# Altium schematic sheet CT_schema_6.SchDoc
size 577 x 363 mm
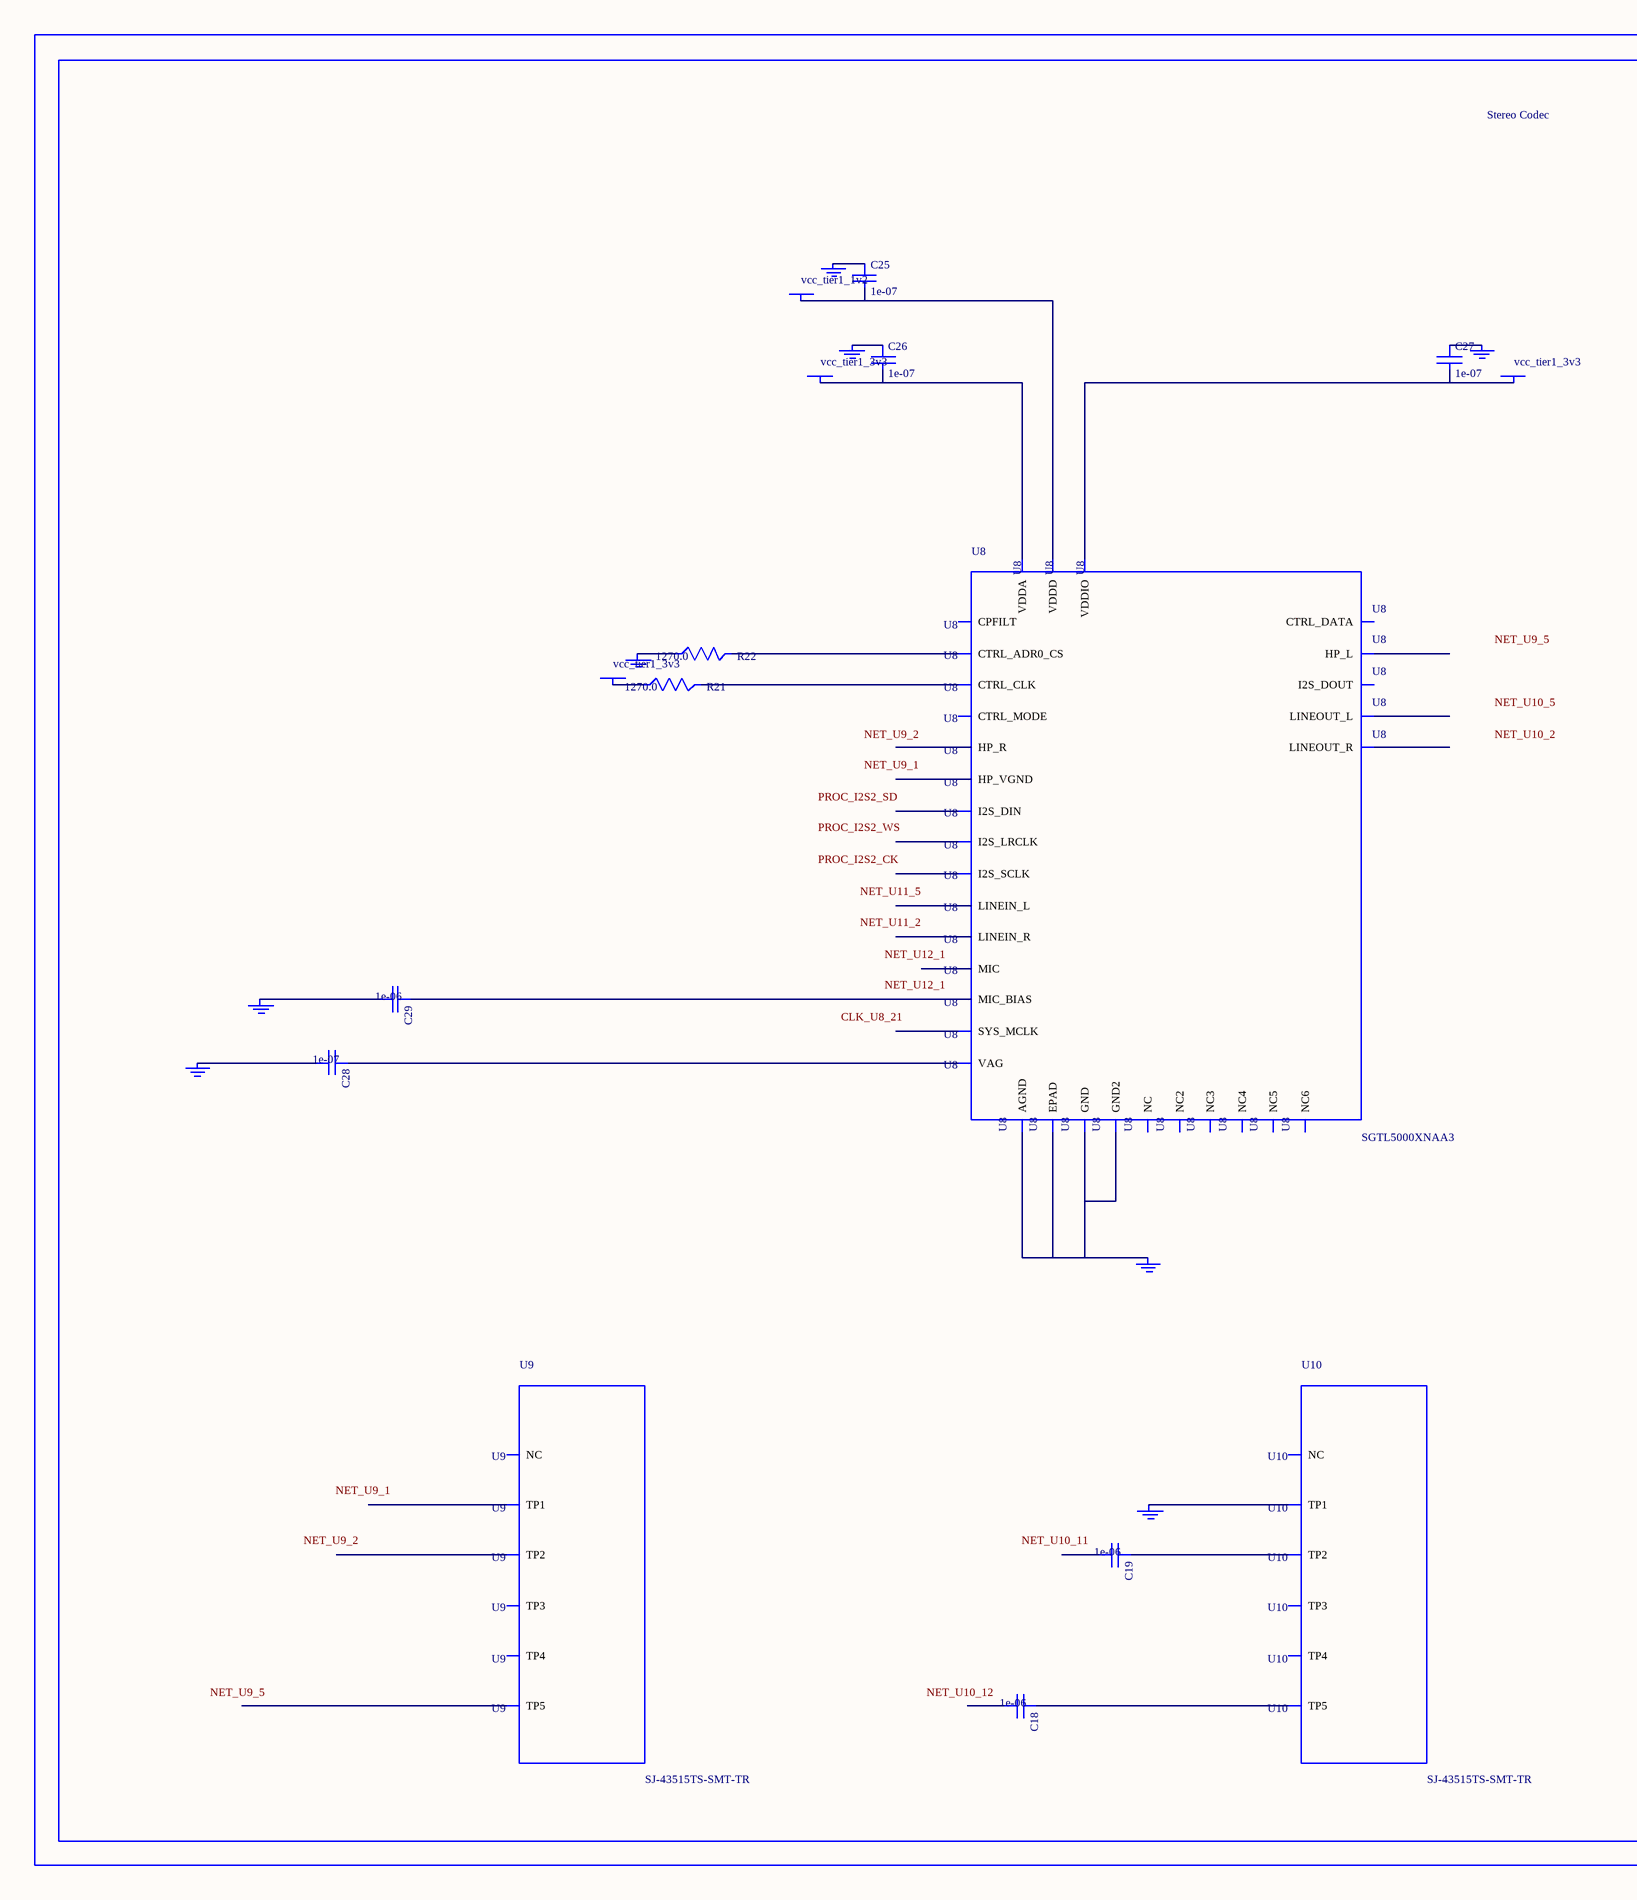
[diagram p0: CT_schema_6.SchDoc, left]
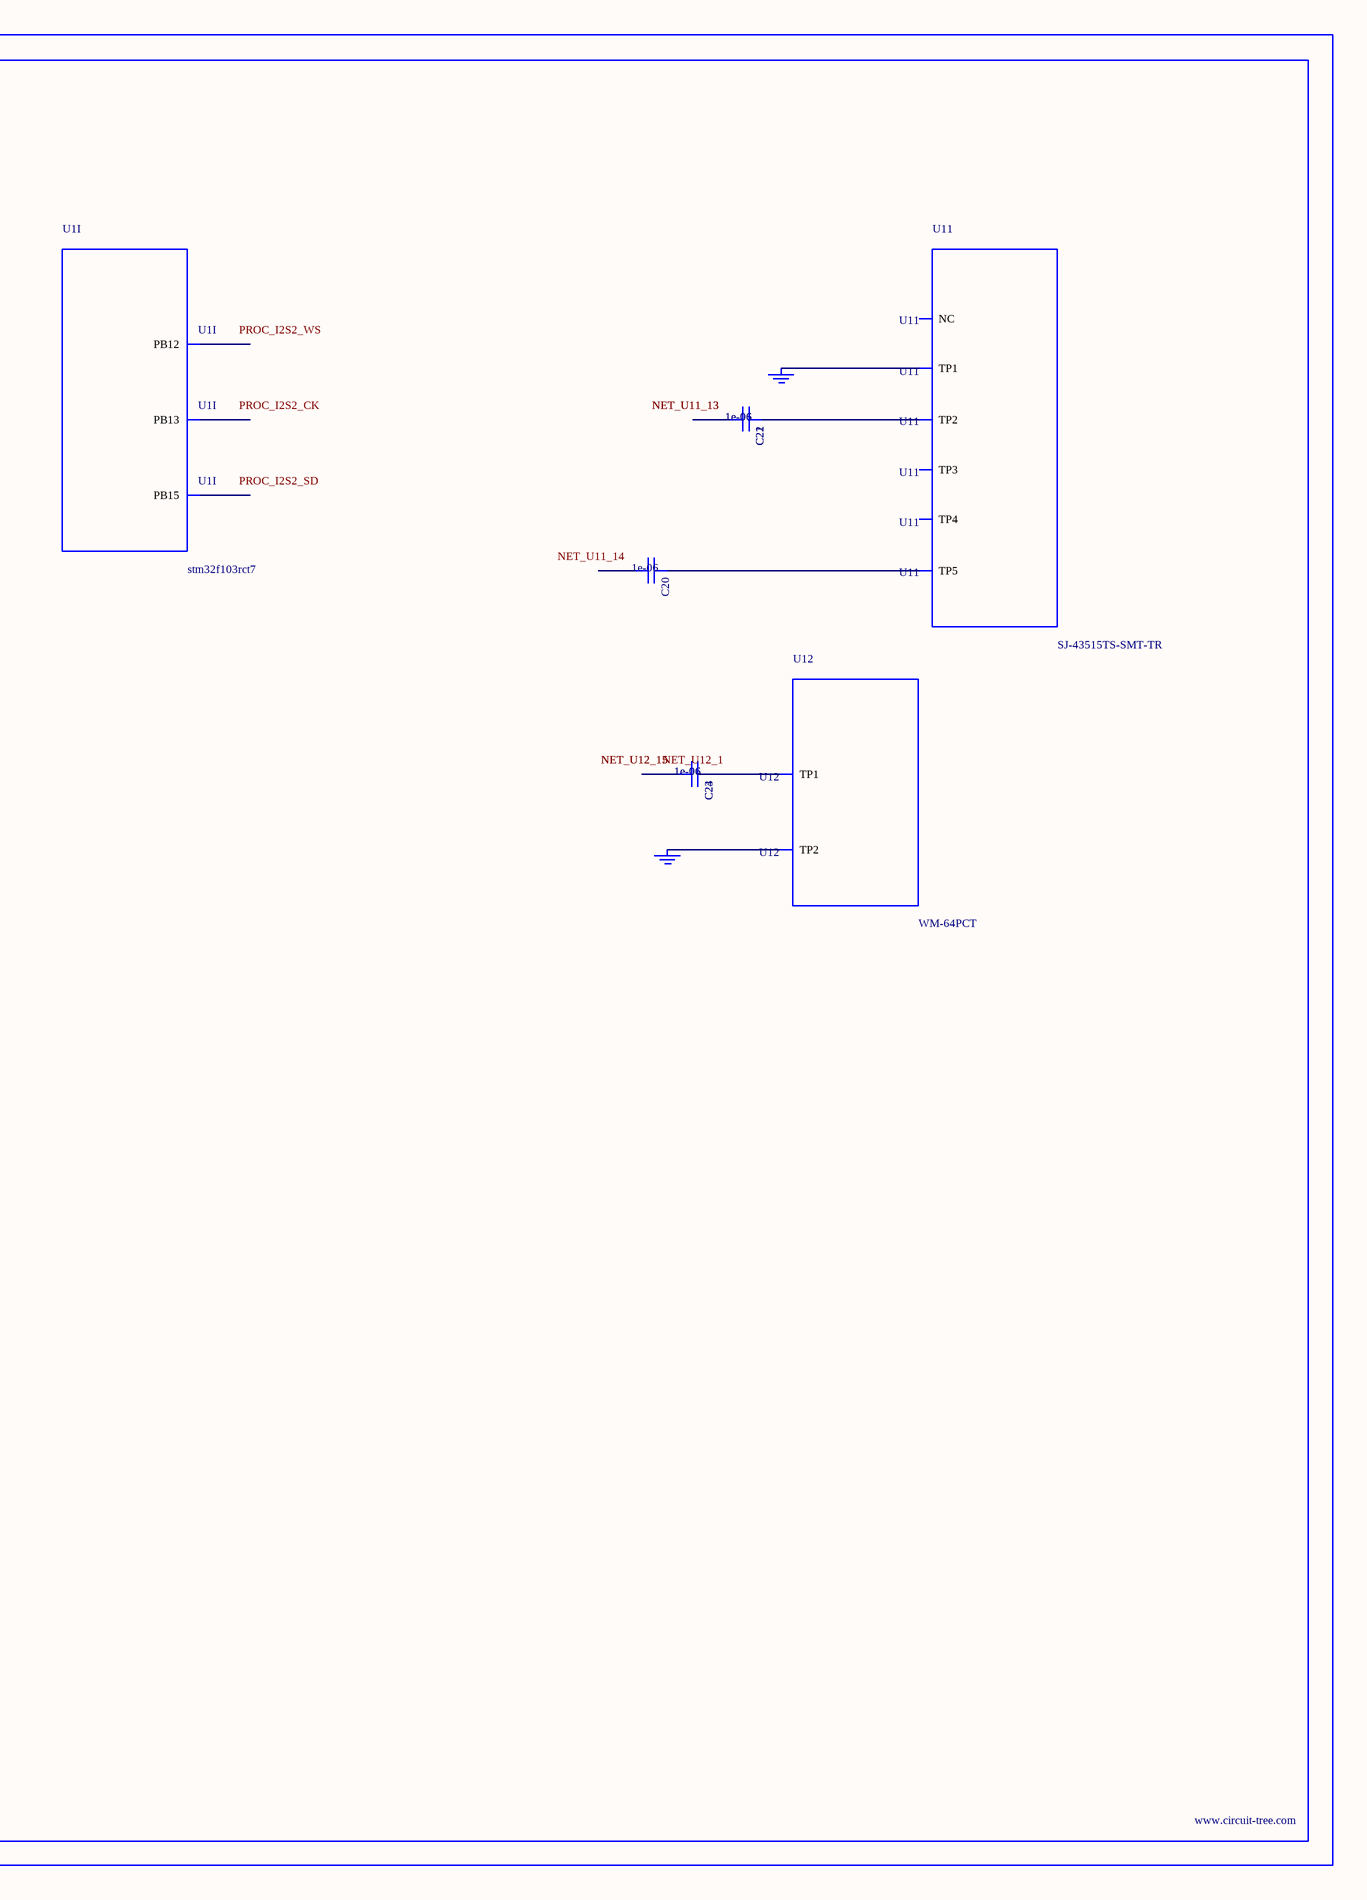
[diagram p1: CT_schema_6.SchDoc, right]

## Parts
BORDER5  (no value)
C18  1e-06  [C0603]
C19  1e-06  [C0603]
C20  1e-06  [C0603]
C21  1e-06  [C0603]
C22  1e-06  [C0603]
C23  1e-06  [C0603]
C24  1e-06  [C0603]
C25  1e-07  [C0402]
C26  1e-07  [C0402]
C27  1e-07  [C0402]
C28  1e-07  [C0402]
C29  1e-06  [C0603]
GND_INSTANCE_5_0  (no value)
GND_INSTANCE_5_1  (no value)
GND_INSTANCE_5_2  (no value)
GND_INSTANCE_5_3  (no value)
GND_INSTANCE_5_4  (no value)
GND_INSTANCE_5_5  (no value)
GND_INSTANCE_5_6  (no value)
GND_INSTANCE_5_7  (no value)
GND_INSTANCE_5_8  (no value)
GND_INSTANCE_5_9  (no value)
GND_INSTANCE_5_10  (no value)
POWER_INSTANCE_5_0  vcc_tier1_3v3
POWER_INSTANCE_5_1  vcc_tier1_3v3
POWER_INSTANCE_5_2  vcc_tier1_3v3
POWER_INSTANCE_5_3  vcc_tier1_1v2
R21  1270.0  [R0603]
R22  1270.0  [R0603]
U1  stm32f103rct7  [LQFP64]  (part I of 9)
U8  SGTL5000XNAA3  [QFN-32]
U9  SJ-43515TS-SMT-TR  [SJ-43515TS-SMT-TR]
U10  SJ-43515TS-SMT-TR  [SJ-43515TS-SMT-TR]
U11  SJ-43515TS-SMT-TR  [SJ-43515TS-SMT-TR]
U12  WM-64PCT  [WM-64PC]

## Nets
NetC18_1: C18.1 U10.5(TP5)
NetC19_1: C19.1 U10.2(TP2)
NetC20_1: C20.1 U11.5(TP5)
NetC21_1: C21.1 C22.1 U11.2(TP2)
NetC21_2: C21.2 C22.2
NetC23_1: C23.1 C24.1 U12.1(TP1)
NetC23_2: C23.2 C24.2
NetC25_1: C25.1 GND_INSTANCE_5_5.0(GND)
NetC25_2: C25.2 POWER_INSTANCE_5_3.0(PWR) U8.30(VDDD)
NetC26_1: C26.1 GND_INSTANCE_5_1.0(GND)
NetC26_2: C26.2 POWER_INSTANCE_5_0.0(PWR) U8.5(VDDA)
NetC27_1: C27.1 GND_INSTANCE_5_4.0(GND)
NetC27_2: C27.2 POWER_INSTANCE_5_1.0(PWR) U8.20(VDDIO)
NetC28_1: C28.1 U8.10(VAG)
NetC28_2: C28.2 GND_INSTANCE_5_2.0(GND)
NetC29_1: C29.1 U8.16(MIC_BIAS)
NetC29_2: C29.2 GND_INSTANCE_5_3.0(GND)
NetGND_INSTANCE_5_0_0: GND_INSTANCE_5_0.0(GND) U8.1(GND) U8.3(GND2) U8.7(AGND) U8.EXP(EPAD)
NetGND_INSTANCE_5_6_0: GND_INSTANCE_5_6.0(GND) R22.1
NetGND_INSTANCE_5_7_0: GND_INSTANCE_5_7.0(GND) U10.1(TP1)
NetGND_INSTANCE_5_8_0: GND_INSTANCE_5_8.0(GND) GND_INSTANCE_5_9.0(GND) U11.1(TP1)
NetGND_INSTANCE_5_10_0: GND_INSTANCE_5_10.0(GND) U12.2(TP2)
NetPOWER_INSTANCE_5_2_0: POWER_INSTANCE_5_2.0(PWR) R21.1
NetR21_2: R21.2 U8.29(CTRL_CLK)
NetR22_2: R22.2 U8.31(CTRL_ADR0_CS)

Not connected (* = marked no-connect by the designer): C18 2; C19 2; C20 2; U1 33(PB12) 34(PB13) 36(PB15); U8 2(HP_R) 4(HP_VGND) 6(HP_L) 8(NC) 9(NC2) 11(LINEOUT_R) 12(LINEOUT_L) 13(LINEIN_R) 14(LINEIN_L) 15(MIC) 17(NC3) 18(CPFILT) 19(NC4) 21(SYS_MCLK) 22(NC5) 23(I2S_LRCLK) 24(I2S_SCLK) 25(I2S_DOUT) 26(I2S_DIN) 27(CTRL_DATA) 28(NC6) 32(CTRL_MODE); U9 1(TP1) 2(TP2) 3(TP3) 4(TP4) 5(TP5) 6(NC); U10 3(TP3) 4(TP4) 6(NC); U11 3(TP3) 4(TP4) 6(NC)

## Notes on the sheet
- Labels drawn without touching a wire or pin: CLK_U8_21, NET_U9_1, NET_U9_2, NET_U9_5, NET_U10_2, NET_U10_5, NET_U10_11, NET_U10_12, NET_U11_2, NET_U11_5, NET_U11_14, NET_U12_1, PROC_I2S2_CK, PROC_I2S2_SD, PROC_I2S2_WS

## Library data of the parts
BORDER5 = BORDER_PAGE5
C18-C24 C29 = C0603C105K3RACTU
C25-C28 = C0402C104K3RACTU
GND_INSTANCE_5_0-GND_INSTANCE_5_10 = GND
POWER_INSTANCE_5_0-POWER_INSTANCE_5_3 = PWR
R21 R22 = RC0603FR-071K27L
